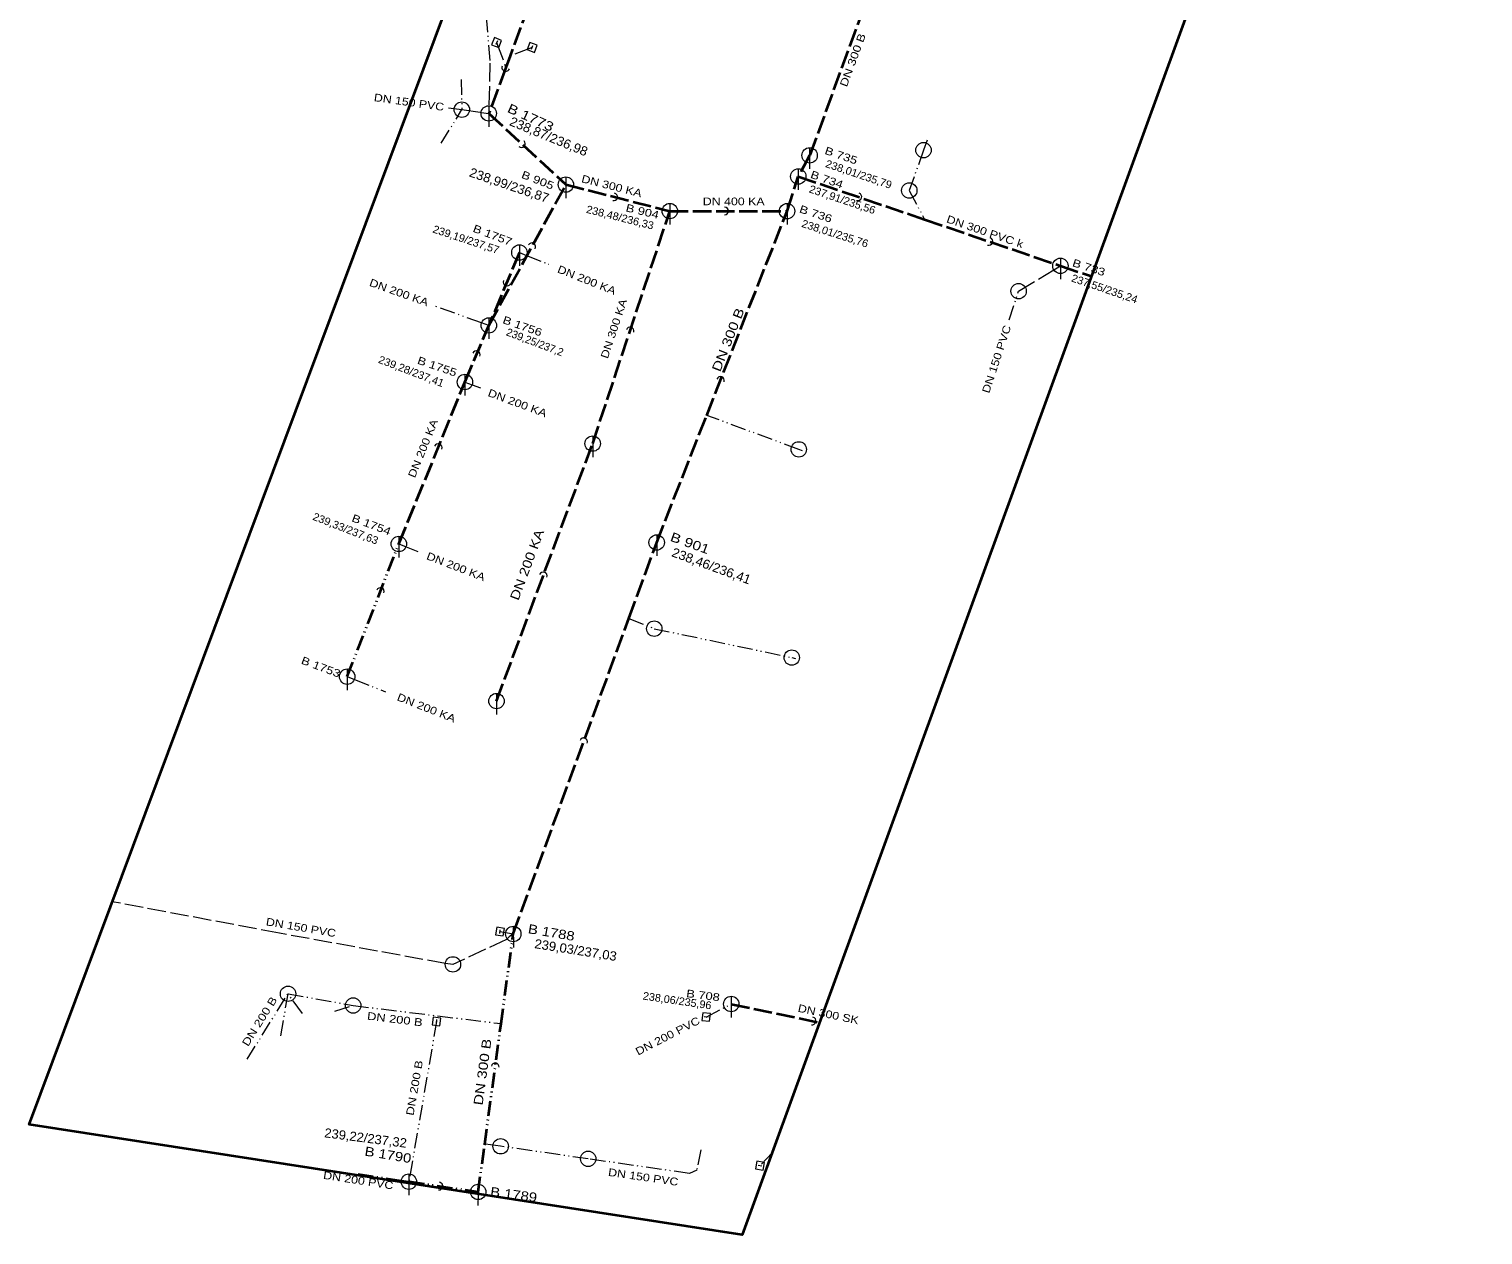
# Model space of a CAD drawing. Extents: x -644344 to -644155, y -1042439 to -1042139.
# Drawn here: x -644344 to -644155.2, y -1042439.4 to -1042282.7 of the extents above; entities that cross this region are included whole.
import ezdxf
from ezdxf.enums import TextEntityAlignment as Align

# ---------------------------------------------------------------- set-up
doc = ezdxf.new("R2010")
doc.units = 0
doc.header["$LTSCALE"] = 0.4
doc.linetypes.add('DASH_DOUBLE_DOT', pattern=[9.2, 5, -1.2, 0.3, -1.2, 0.3, -1.2])
doc.linetypes.add('LONG_DASHED', pattern=[7.5, 6, -1.5])
for name, color, linetype, lineweight in [('10', 7, 'Continuous', 13), ('14', 7, 'Continuous', 13), ('23', 7, 'LONG_DASHED', 35), ('24', 7, 'DASH_DOUBLE_DOT', 35), ('25', 7, 'LONG_DASHED', 35), ('33', 7, 'LONG_DASHED', 13), ('34', 7, 'DASH_DOUBLE_DOT', 13), ('35', 7, 'LONG_DASHED', 13), ('36', 7, 'DASH_DOUBLE_DOT', 13), ('37', 7, 'LONG_DASHED', 13), ('38', 7, 'DASH_DOUBLE_DOT', 13), ('63', 7, 'Continuous', 35)]:
    doc.layers.add(name, color=color, linetype=linetype, lineweight=lineweight)
doc.layers.add('29', color=7, linetype='Continuous')
doc.layers.add('39', color=7, linetype='Continuous')

msp = doc.modelspace()

# ---------------------------------------------------------------- linework, layer by layer
at = {"layer": '10'}
for p, q in [((-644283.159, -1042284.238), (-644283.343, -1042284.702)), ((-644278.727, -1042285.328), (-644278.549, -1042284.86)), ((-644284.275, -1042292.679), (-644284.275, -1042295.427)), ((-644242.61, -1042298.13), (-644242.61, -1042300.878)), ((-644244.08, -1042300.87), (-644244.08, -1042303.618)), ((-644274.26, -1042301.92), (-644274.26, -1042304.668)), ((-644260.76, -1042305.36), (-644260.76, -1042308.108)), ((-644245.537, -1042305.378), (-644245.537, -1042308.126)), ((-644280.3, -1042310.75), (-644280.3, -1042313.498)), ((-644210.04, -1042312.48), (-644210.04, -1042315.228)), ((-644284.27, -1042320.22), (-644284.27, -1042322.968)), ((-644287.37, -1042327.57), (-644287.37, -1042330.318)), ((-644270.78, -1042335.57), (-644270.78, -1042338.318)), ((-644295.95, -1042348.61), (-644295.95, -1042351.358)), ((-644262.47, -1042348.42), (-644262.47, -1042351.168)), ((-644302.657, -1042365.85), (-644302.657, -1042368.598)), ((-644283.27, -1042369.02), (-644283.27, -1042371.768)), ((-644282.858, -1042400.217), (-644282.782, -1042399.723)), ((-644281.103, -1042399.281), (-644281.066, -1042402.027)), ((-644252.785, -1042408.379), (-644252.785, -1042411.127)), ((-644255.802, -1042411.098), (-644256.298, -1042411.042)), ((-644291.081, -1042411.888), (-644291.019, -1042411.392)), ((-644294.65, -1042431.46), (-644294.65, -1042434.208)), ((-644248.801, -1042430.427), (-644249.295, -1042430.347)), ((-644285.611, -1042432.792), (-644285.712, -1042435.538))]:
    msp.add_line(p, q, dxfattribs=at)
for points in [[(-644283.531, -1042283.821), (-644283.9, -1042284.75), (-644282.971, -1042285.119), (-644282.602, -1042284.19)], [(-644278.349, -1042285.74), (-644277.992, -1042284.805), (-644278.927, -1042284.448), (-644279.284, -1042285.383)], [(-644282.402, -1042400.541), (-644282.249, -1042399.552), (-644283.238, -1042399.399), (-644283.391, -1042400.388)], [(-644290.616, -1042412.198), (-644290.492, -1042411.206), (-644291.484, -1042411.082), (-644291.608, -1042412.074)], [(-644255.497, -1042410.63), (-644256.49, -1042410.517), (-644256.603, -1042411.51), (-644255.61, -1042411.623)], [(-644248.475, -1042429.972), (-644249.463, -1042429.814), (-644249.621, -1042430.802), (-644248.633, -1042430.96)]]:
    msp.add_lwpolyline(points, close=True, dxfattribs=at)
for centre, radius in [((-644287.7663, -1042293.1848), 1), ((-644284.2747, -1042293.6793), 1.0002), ((-644227.8232, -1042298.4496), 1), ((-644242.6097, -1042299.1303), 1.0002), ((-644244.0797, -1042301.8703), 1.0002), ((-644274.2597, -1042302.9203), 1.0002), ((-644229.6697, -1042303.6902), 1), ((-644260.7597, -1042306.3603), 1.0002), ((-644245.5367, -1042306.3783), 1.0002), ((-644280.2997, -1042311.7503), 1.0002), ((-644210.0397, -1042313.4803), 1.0002), ((-644215.4697, -1042316.7702), 1), ((-644284.2697, -1042321.2203), 1.0002), ((-644287.3697, -1042328.5703), 1.0002), ((-644270.7797, -1042336.5703), 1.0002), ((-644244.0157, -1042337.3232), 1), ((-644295.9497, -1042349.6103), 1.0002), ((-644262.4697, -1042349.4203), 1.0002), ((-644262.7838, -1042360.6157), 1), ((-644244.9277, -1042364.3707), 1), ((-644302.6567, -1042366.8503), 1.0002), ((-644283.2697, -1042370.0203), 1.0002), ((-644281.0897, -1042400.2803), 1.0002), ((-644288.9297, -1042404.2301), 1), ((-644310.3393, -1042408.0521), 1), ((-644301.8827, -1042409.5688), 1), ((-644252.7847, -1042409.3793), 1.0002), ((-644282.7297, -1042427.8655), 1), ((-644271.3602, -1042429.499), 1), ((-644294.6497, -1042432.4603), 1.0002), ((-644285.6477, -1042433.7913), 1.0002)]:
    msp.add_circle(centre, radius, dxfattribs=at)
at = {"layer": '14'}
for centre, start, end in [((-644282.0646, -1042287.7029), 159.69712, 339.69713), ((-644280.029, -1042297.5976), 227.30178, 47.30178), ((-644268.0593, -1042304.5075), 255.75624, 75.75624), ((-644236.3481, -1042304.4996), 251.22009, 71.22009), ((-644253.6481, -1042306.3688), 269.93225, 89.93225), ((-644278.6834, -1042311.0085), 331.32158, 151.32158), ((-644219.3278, -1042310.3037), 251.11774, 71.11774), ((-644281.9053, -1042315.5783), 157.25566, 337.25566), ((-644265.9269, -1042321.9393), 341.65044, 161.65044), ((-644285.8958, -1042325.0315), 337.13151, 157.13151), ((-644254.186, -1042328.3641), 338.52501, 158.52501), ((-644290.8463, -1042337.0968), 337.81463, 157.81463), ((-644277.1994, -1042353.7632), 339.52471, 159.52471), ((-644298.3537, -1042355.7908), 338.74109, 158.74109), ((-644271.9577, -1042375.3168), 339.09584, 159.09584), ((-644242.2791, -1042411.5819), 258.15994, 78.15994), ((-644283.4358, -1042417.531), 352.25444, 172.25444), ((-644290.7463, -1042433.0378), 261.58941, 81.58941)]:
    msp.add_arc(centre, 0.5, start, end, dxfattribs=at)
at = {"layer": '23'}
for p, q in [((-644269.735, -1042254.389), (-644281.51, -1042286.207)), ((-644284.275, -1042293.679), (-644274.26, -1042302.92)), ((-644242.61, -1042299.13), (-644244.08, -1042301.87)), ((-644284.27, -1042321.22), (-644274.26, -1042302.92)), ((-644274.26, -1042302.92), (-644260.76, -1042306.36)), ((-644255.974, -1042332.907), (-644245.537, -1042306.378)), ((-644280.3, -1042311.75), (-644284.27, -1042321.22)), ((-644287.37, -1042328.57), (-644284.27, -1042321.22)), ((-644295.95, -1042349.61), (-644287.37, -1042328.57)), ((-644262.47, -1042349.42), (-644255.974, -1042332.907)), ((-644252.785, -1042409.379), (-644241.318, -1042411.783))]:
    msp.add_line(p, q, dxfattribs=at)
for points in [[(-644230.612, -1042266.383), (-644232.478, -1042271.477), (-644232.478, -1042271.477), (-644242.61, -1042299.13)], [(-644281.51, -1042286.207), (-644282.06, -1042287.692), (-644284.275, -1042293.679)], [(-644260.76, -1042306.36), (-644245.537, -1042306.378), (-644244.08, -1042301.87)], [(-644244.08, -1042301.87), (-644227.67, -1042307.45), (-644210.04, -1042313.48), (-644206.013, -1042314.827)], [(-644266.079, -1042359.279), (-644262.47, -1042349.42), (-644262.47, -1042349.42)], [(-644281.09, -1042400.28), (-644266.079, -1042359.279), (-644266.079, -1042359.279)]]:
    msp.add_lwpolyline(points, dxfattribs=at)
at = {"layer": '24'}
for p, q in [((-644302.657, -1042366.85), (-644295.95, -1042349.61)), ((-644282.674, -1042411.925), (-644281.09, -1042400.28)), ((-644284.802, -1042427.568), (-644282.674, -1042411.925)), ((-644294.65, -1042432.46), (-644285.648, -1042433.791)), ((-644285.704, -1042434.057), (-644285.648, -1042433.791))]:
    msp.add_line(p, q, dxfattribs=at)
msp.add_lwpolyline([(-644285.648, -1042433.791), (-644284.802, -1042427.568), (-644284.802, -1042427.568)], dxfattribs=at)
at = {"layer": '25'}
for p, q in [((-644270.78, -1042336.57), (-644260.76, -1042306.36)), ((-644283.27, -1042370.02), (-644270.78, -1042336.57))]:
    msp.add_line(p, q, dxfattribs=at)
at = {"layer": '33'}
for p, q in [((-644284.126, -1042287.15), (-644284.252, -1042292.679)), ((-644287.766, -1042293.185), (-644285.265, -1042293.539)), ((-644285.265, -1042293.539), (-644284.275, -1042293.679)), ((-644284.252, -1042292.679), (-644284.275, -1042293.679))]:
    msp.add_line(p, q, dxfattribs=at)
msp.add_lwpolyline([(-644215.47, -1042316.77), (-644210.895, -1042313.998), (-644210.04, -1042313.48)], dxfattribs=at)
at = {"layer": '34'}
for p, q in [((-644287.858, -1042289.264), (-644287.766, -1042293.185)), ((-644290.446, -1042297.536), (-644287.766, -1042293.185)), ((-644227.362, -1042297.14), (-644227.824, -1042298.45)), ((-644229.67, -1042303.69), (-644227.67, -1042307.45)), ((-644280.3, -1042311.75), (-644279.37, -1042312.12)), ((-644279.37, -1042312.12), (-644276.49, -1042313.267)), ((-644285.212, -1042320.884), (-644291.335, -1042318.698)), ((-644284.27, -1042321.22), (-644285.212, -1042320.884)), ((-644244.015, -1042337.323), (-644255.974, -1042332.907)), ((-644243.551, -1042337.495), (-644244.015, -1042337.323)), ((-644311.271, -1042413.499), (-644310.34, -1042408.052)), ((-644304.265, -1042410.327), (-644301.883, -1042409.569)), ((-644295.638, -1042432.308), (-644301.535, -1042431.4)), ((-644294.65, -1042432.46), (-644295.638, -1042432.308)), ((-644294.65, -1042432.46), (-644294.876, -1042432.635))]:
    msp.add_line(p, q, dxfattribs=at)
for points in [[(-644284.616, -1042281.121), (-644284.126, -1042287.15), (-644284.126, -1042287.15)], [(-644289.522, -1042292.936), (-644287.766, -1042293.185), (-644287.766, -1042293.185)], [(-644227.824, -1042298.45), (-644229.67, -1042303.69), (-644229.67, -1042303.69)], [(-644216.701, -1042320.511), (-644215.47, -1042316.77), (-644215.47, -1042316.77)], [(-644287.37, -1042328.57), (-644286.432, -1042328.919), (-644285.369, -1042329.315)], [(-644295.95, -1042349.61), (-644295.017, -1042349.971), (-644293.474, -1042350.569)], [(-644266.079, -1042359.279), (-644262.784, -1042360.616), (-644262.784, -1042360.616), (-644244.928, -1042364.371), (-644244.424, -1042364.477)], [(-644302.657, -1042366.85), (-644301.727, -1042367.218), (-644297.682, -1042368.817)], [(-644310.34, -1042408.052), (-644301.883, -1042409.569), (-644282.674, -1042411.925)]]:
    msp.add_lwpolyline(points, dxfattribs=at)
at = {"layer": '35'}
for p, q in [((-644283.251, -1042284.47), (-644282.06, -1042287.692)), ((-644278.638, -1042285.094), (-644281.51, -1042286.207)), ((-644282.82, -1042399.97), (-644281.09, -1042400.28))]:
    msp.add_line(p, q, dxfattribs=at)
at = {"layer": '36'}
for p, q in [((-644315.655, -1042416.567), (-644310.34, -1042408.052)), ((-644256.05, -1042411.07), (-644252.785, -1042409.379)), ((-644291.05, -1042411.64), (-644294.65, -1042432.46)), ((-644247.484, -1042428.716), (-644249.048, -1042430.387))]:
    msp.add_line(p, q, dxfattribs=at)
at = {"layer": '37'}
for points in [[(-644288.93, -1042404.23), (-644289.88, -1042404.12), (-644311.47, -1042400.18), (-644333.165, -1042396.095)], [(-644281.872, -1042400.904), (-644281.99, -1042401.01), (-644288.93, -1042404.23)], [(-644281.09, -1042400.28), (-644281.61, -1042400.67), (-644281.872, -1042400.904)]]:
    msp.add_lwpolyline(points, dxfattribs=at)
at = {"layer": '38'}
for p, q in [((-644308.476, -1042410.603), (-644310.34, -1042408.052)), ((-644282.729, -1042427.866), (-644284.802, -1042427.568)), ((-644271.36, -1042429.499), (-644282.729, -1042427.866))]:
    msp.add_line(p, q, dxfattribs=at)
msp.add_lwpolyline([(-644256.749, -1042428.326), (-644257.269, -1042430.976), (-644258.2, -1042431.39), (-644271.36, -1042429.499)], dxfattribs=at)
at = {"layer": '63'}
msp.add_lwpolyline([(-644237.01, -1042138.605), (-644155.176, -1042175.215), (-644251.367, -1042439.381), (-644343.968, -1042425.024)], close=True, dxfattribs=at)

# ---------------------------------------------------------------- texts
at = {"layer": '29'}
for s, height, rotation, width, p in [('DN 300 B', 1, 69.879, 1.25, (-644236.5377, -1042286.913)), ('238,87/236,98', 1.2, 337.698, 1.05, (-644276.7122, -1042297.2222)), ('238,01/235,79', 1, 341.334, 1.05, (-644236.388, -1042302.058)), ('238,99/236,87', 1.2, 341.199, 1.05, (-644281.8099, -1042303.5708)), ('DN 300 KA', 1, 345.756, 1.2, (-644268.429, -1042303.5901)), ('237,91/235,56', 1, 341.389, 1.05, (-644238.5166, -1042305.3418)), ('DN 400 KA', 1, 359.932, 1.2, (-644252.4686, -1042305.6078)), ('238,48/236,33', 1, 345.847, 1.05, (-644267.3423, -1042307.6692)), ('DN 300 PVC k', 1, 341.118, 1.2, (-644219.9918, -1042309.4962)), ('239,19/237,57', 1, 341.651, 1.05, (-644287.3734, -1042310.5325)), ('238,01/235,76', 1, 342.321, 1.05, (-644239.4603, -1042309.7649)), ('237,55/235,24', 1, 341.126, 1.05, (-644204.4682, -1042316.926)), ('DN 300 KA', 1, 71.65, 1.2, (-644267.5642, -1042321.8014)), ('DN 300 B', 1.2, 68.525, 1.25, (-644252.64, -1042323.2957)), ('239,28/237,41', 1, 339.068, 1.05, (-644294.5121, -1042327.652)), ('DN 200 KA', 1, 67.815, 1.2, (-644292.359, -1042337.3908)), ('239,33/237,63', 1, 338.661, 1.05, (-644303.0534, -1042348.0709)), ('DN 200 KA', 1.2, 69.525, 1.2, (-644278.7515, -1042352.5249)), ('B 901', 1.2, 340.196, 1.25, (-644258.3463, -1042350.0642)), ('238,46/236,41', 1.2, 339.953, 1.05, (-644255.5667, -1042353.0313)), ('239,03/237,03', 1.2, 350.979, 1.05, (-644273.0821, -1042402.9515)), ('238,06/235,96', 1, 351.699, 1.05, (-644259.8737, -1042409.4341)), ('DN 300 SK', 1, 348.16, 1.2, (-644240.2776, -1042411.1929)), ('DN 300 B', 1.2, 82.254, 1.25, (-644284.4967, -1042418.2879)), ('239,22/237,32', 1.2, 352.667, 1.05, (-644300.3411, -1042427.3735))]:
    msp.add_text(s, height=height, rotation=rotation, dxfattribs=dict(at, width=width)).set_placement(p, align=Align.CENTER)
for s, height, rotation, width, p in [('B 1773', 1.2, 335.711, 1.25, (-644281.973, -1042293.452)), ('B 735', 1, 341.12, 1.25, (-644240.74, -1042298.91)), ('B 905', 1, 338.754, 1.25, (-644280.132, -1042302.016)), ('B 734', 1, 340.744, 1.25, (-644242.592, -1042302.013)), ('B 904', 1, 346.683, 1.25, (-644266.559, -1042306.383)), ('B 736', 1, 341.615, 1.25, (-644244.032, -1042306.511)), ('B 1757', 1, 339.33, 1.25, (-644286.434, -1042309.016)), ('B 733', 1, 342.283, 1.25, (-644208.58, -1042313.503)), ('B 1756', 1, 340.572, 1.25, (-644282.562, -1042320.898)), ('B 1755', 1, 341.102, 1.25, (-644293.64, -1042326.164)), ('B 1754', 1, 339.249, 1.25, (-644302.167, -1042346.639)), ('B 1753', 1, 339.445, 1.25, (-644308.732, -1042365.13)), ('B 1788', 1.2, 350.348, 1.2, (-644279.25, -1042400.168)), ('B 708', 1, 352.723, 1.25, (-644258.673, -1042408.472)), ('B 1790', 1.2, 350.644, 1.2, (-644300.462, -1042429.061)), ('B 1789', 1.2, 352.428, 1.2, (-644284.138, -1042434.324))]:
    msp.add_text(s, height=height, rotation=rotation, dxfattribs=dict(at, width=width)).set_placement(p)
msp.add_text('239,25/237,2', height=1, rotation=339.226, dxfattribs=at).set_placement((-644278.4553, -1042323.8598), align=Align.CENTER)
at = {"layer": '39'}
for s, rotation, width, p in [('DN 150 PVC', 351.929, 1.2, (-644294.6922, -1042292.7076)), ('DN 200 KA', 338.284, 1.2, (-644271.734, -1042315.7843)), ('DN 200 KA', 340.353, 1.2, (-644296.0971, -1042317.4051)), ('DN 150 PVC', 71.786, 1.2, (-644217.8633, -1042325.7493)), ('DN 200 KA', 339.568, 1.2, (-644280.7205, -1042331.7679)), ('DN 200 KA', 338.816, 1.2, (-644288.7157, -1042353.012)), ('DN 200 KA', 338.431, 1.2, (-644292.5528, -1042371.3633)), ('DN 150 PVC', 350.261, 1.2, (-644308.7421, -1042399.92)), ('DN 200 B', 58.028, 1.25, (-644313.6167, -1042411.9018)), ('DN 200 B', 353.008, 1.25, (-644296.5249, -1042411.8418)), ('DN 200 PVC', 27.38, 1.2, (-644260.8149, -1042413.9759)), ('DN 200 B', 80.19, 1.25, (-644293.4343, -1042420.3632)), ('DN 200 PVC', 351.248, 1.2, (-644301.2881, -1042432.7773)), ('DN 150 PVC', 351.823, 1.2, (-644264.2761, -1042432.351))]:
    msp.add_text(s, height=1, rotation=rotation, dxfattribs=dict(at, width=width)).set_placement(p, align=Align.CENTER)

doc.saveas('drawing.dxf')
